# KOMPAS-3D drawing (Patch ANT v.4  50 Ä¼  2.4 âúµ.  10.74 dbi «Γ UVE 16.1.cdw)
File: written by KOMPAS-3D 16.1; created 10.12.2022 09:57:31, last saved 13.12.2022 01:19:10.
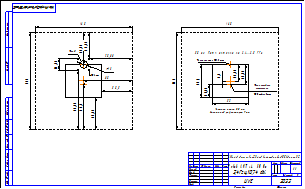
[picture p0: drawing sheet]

Sheet 1: custom format 500 x 310 mm, landscape

Title block, sheet 1: name: Patch ANT v.4  50 Ом / 2,4Ггц.10,74 dbi.; designation: https://www.lan23.ru/forum/node/851/page32; material: UVE; scale: 1:1; sheets: 1; organisation: 2022; stored path: G:\Patch ANT v.4  50 Ом от uve.cdw

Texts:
  высота над рефлектором 7мм
  50 ом Патч антенна на 2.4...2.5 ГГц
  Точка нулевого
  потенциала
  Ø Стойки 5mm
  Толщина патча 0,5 мм
  Точка запитки Ø 1,5 mm
  Type N
  Ø 2mm
Dimensions and other numbers on the sheet: 52,75; 50,5; 80; 74,5; 53,25; 18,24; 13; 70,88; 44,07; 97,69; 160; 21,75; 59; 26,75; 54,5; 5,5; 32,25; 1:1; 1; 2,4Ггц.10,74 dbi.; 2022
